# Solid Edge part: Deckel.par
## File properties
Author: Heike
Template: Normal.par
Last saved by: Heike
Revision: 40
Application: Solid Edge
Dichte: 1,024 kg/dm^3
Genauigkeit: 0,990
Material: ABS Plastik, mittelfest
Teilflächenrmatvorlage: Schwarz
Füllformatvorlage: ANSI34(Plastic)
Virtuelle Formatvorlage: Schwarz (hell glänzend)
Coef. of Thermal Exp: 5.8e-05
Thermal Conductivity: 2.0
Specific Heat: 0.0
Modulus of Elasticity: 2275269810.0
Poission's Ratio: 0.4
Yield Stress: 43436969.1
Ultimate Stress: 0.0
Elongation: 0.0
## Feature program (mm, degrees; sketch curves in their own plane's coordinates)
sketch for "unnamed Protrusion 1" plane through (0, 0, 0) normal (0, 0, 1) x-axis (1, 0, 0)
  line (-30, 30) -> (30, 30)
  line (30, 30) -> (30, -30)
  line (30, -30) -> (-30, -30)
  line (-30, -30) -> (-30, 30)
  dimension (linear) = 30
  dimension (linear) = 30
extrude "unnamed Protrusion 1" add finite 14.6 along +normal
fillet "Verrundung" radius 8
chamfer "Fase1" setback 3
thinwall "Dünnwand"  Thickness = 1 mm
sketch for "unnamed Cutout 1" plane through (0, 0, 0) normal (0, 0, -1) x-axis (-1, 0, 0)
  line (0, 0) -> (0, 0)
  line (20, 20) -> (-20, 20)
  line (-20, 20) -> (-20, -20)
  line (-20, -20) -> (20, -20)
  line (20, 20) -> (20, -20)
  dimension (linear) = 20
extrude "unnamed Cutout 1" cut through along -normal
fillet "Verrundung_2" radius 2
logasc func "SpaltP"  LipOrGrooveWidth = 0.4 mm; LipOrGrooveHeight = 2 mm
chamfer "Fase_2" setback 1
sketch for "Niederhalter" plane through (0, 0, 1) normal (0, 0, 1) x-axis (1, 0, 0)
extrude "Niederhalter" add finite 4.4 along +normal
sketch for "Raste" plane through (29, 0, 11.2071) normal (-1, 0, 0) x-axis (0, 0, 1)
extrude "Raste" add finite 0.8 along +normal
mirror "unnamed Mirror 1" of "Raste", "Niederhalter" about plane through (0, 0, 0) normal (1, 0, 0)
extrude "unnamed Protrusion 2" add finite 4.4
extrude "unnamed Protrusion 3" add finite 0.8
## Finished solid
Body 1: solid body, 57 faces, 132 edges, 80 vertices.
  Faces by surface: plane 35, cone 12, cylinder 10
  Edges by curve: line 96, circle 36
Bounding box of the edges (mm): 60.000 x 60.000 x 14.600, from (-30, -30, 0) to (30, 30, 14.6).
Cylindrical faces by radius (mm): R2.5 x2, R7 x4, R8 x4
Conical faces (half-angle, radius in mm at the cone's reference point): 45 deg R3.4 x4, 45 deg R4.2929 x4, 45 deg R5 x4
Planar faces by outward normal: +x 5, +y 4, +z 4, -x 5, -y 4, -z 1, oblique 12
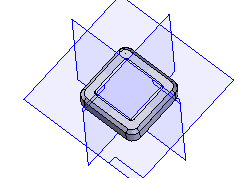
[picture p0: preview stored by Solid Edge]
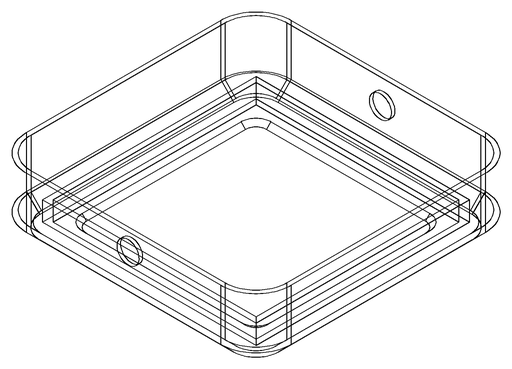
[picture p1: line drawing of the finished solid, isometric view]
